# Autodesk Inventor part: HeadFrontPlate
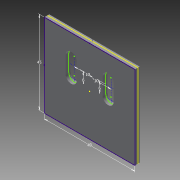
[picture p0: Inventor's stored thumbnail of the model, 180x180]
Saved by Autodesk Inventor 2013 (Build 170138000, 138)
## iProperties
Created: 2013-04
Part Number: HeadFrontPlate
Material: Generic
Document SubType Name: Modeling
Designer: frankenteddy
Density: 1 g/cm^3
Author: frankenteddy
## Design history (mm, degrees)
node "Blocks"
  sketch "Block3"
    geometry: L1 (42.096, -1.116)-(42.096, 7.884); L2 (48.096, 7.884)-(48.096, -1.116); L3 (62.096, -1.116)-(62.096, 7.884); L4 (68.096, 7.884)-(68.096, -1.116); L5 (78.596, -14.116)-(31.596, -14.116); L6 (78.596, 32.884)-(78.596, -14.116); L7 (31.596, 32.884)-(78.596, 32.884); L8 (31.596, -14.116)-(31.596, 32.884); L9 (55.096, -14.116)-(55.096, 32.884); L10 (78.596, 9.384)-(31.596, 9.384); A1 r 3 centre (45.096, 7.884) between (48.096, 7.884) and (42.096, 7.884); A2 r 3 centre (45.096, -1.116) between (42.096, -1.116) and (48.096, -1.116); A3 r 3 centre (65.096, -1.116) between (62.096, -1.116) and (68.096, -1.116); A4 r 3 centre (65.096, 7.884) between (68.096, 7.884) and (62.096, 7.884); 2 further points
    constraints: 20 end point, 8 point on circle, 4 centre point, 4 midpoint
sketch "Sketch1"
  geometry: L1 (-24.5, 22.5)-(24.5, 22.5); L2 (24.5, 22.5)-(24.5, -22.5); L3 (24.5, -22.5)-(-24.5, -22.5); L4 (-24.5, -22.5)-(-24.5, 22.5); 3 further points
  constraints: 8 end point, 2 midpoint, 2 parallel, 1 horizontal, 1 horizontal alignment, 1 perpendicular, 1 vertical alignment
  dimensions: "d0" = 49 distance of L2.end L3.end; "d1" = 45 distance of L1.end L2.end
extrude "Extrusion1" new body sketch "Sketch1" distance "d2" = 1.62; taper "d3" = 0 deg
sketch "Sketch2"
  geometry: L1 (-24.5, -22.5)-(24.5, -22.5) reference; L2 (24.5, -22.5)-(24.5, 22.5) reference; L3 (24.5, 22.5)-(-24.5, 22.5) reference; L4 (-24.5, 22.5)-(-24.5, -22.5) reference; L5 (0, 22.5)-(0, -22.5); L6 (24.5, 0)-(-24.5, 0); L7 (-13, -10.5)-(-13, -1.5); L8 (-7, -1.5)-(-7, -10.5); L9 (7, -10.5)-(7, -1.5); L10 (13, -1.5)-(13, -10.5); L11 (0, -23.5)-(0, 23.5); L12 (23.5, 0)-(-23.5, 0); L13 (-16.531, 18.34)-(0, 18.34); L14 (0, 18.34)-(0, 13.374); L15 (0, 13.374)-(-16.531, 13.374); L16 (-16.531, 13.374)-(-16.531, 18.34); L17 (-9.001, 12.258)-(-6.651, 8.188); L18 (-6.651, 8.188)-(-11.351, 8.188); L19 (-11.351, 8.188)-(-9.001, 12.258); L20 (-7.97, 18.942)-(-10.008, 22.473); L21 (-10.008, 22.473)-(-5.931, 22.473); L22 (-5.931, 22.473)-(-7.97, 18.942); L23 (0, 14.315)-(-4.713, 22.479); L24 (-4.713, 22.479)-(4.713, 22.479); L25 (4.713, 22.479)-(0, 14.315); L26 (-3.247, 12.258)-(-0.897, 8.188); L27 (-0.897, 8.188)-(-5.596, 8.188); L28 (-5.596, 8.188)-(-3.247, 12.258); L29 (-22.323, 0.851)-(-19.711, -2.143); L30 (-19.711, -2.143)-(-22.851, -4.882); L31 (-22.851, -4.882)-(-20.051, -8.092); L32 (-20.051, -8.092)-(-23.425, -11.035); L33 (-19.388, -10.962)-(-16.015, -8.019); L34 (-16.015, -8.019)-(-18.545, -5.119); L35 (-18.545, -5.119)-(-15.51, -2.471); L36 (-15.51, -2.471)-(-18.545, 1.007); L37 (-10, 1.5)-(-10, -13.5); L38 (10, 1.5)-(10, -13.5); L39 (7, -6)-(13, -6); L40 (-7, -6)-(-13, -6); L41 (-18.545, 1.007)-(-17.226, 4.687); L42 (-19.388, -10.962)-(-16.015, -16.078); L43 (-22.323, 0.851)-(-17.226, 4.687); L44 (-16.015, -16.078)-(-23.425, -11.035); L45 (0, 22.5)-(0, -22.5); C1 r 3.587 at (-18.339, 15.894); C2 r 5.941 at (-18.339, 15.894); C3 r 1.247 at (-11.868, 20.707); C4 r 1.839 at (-16.531, 7.036); C5 r 1.413 at (-21.398, 7.812); C6 r 2.671 at (-20.541, -18.762); C7 r 1.818 at (-20.541, -18.762); A1 r 3 centre (-10, -1.5) between (-7, -1.5) and (-13, -1.5); A2 r 3 centre (-10, -10.5) between (-13, -10.5) and (-7, -10.5); A3 r 3 centre (10, -10.5) between (7, -10.5) and (13, -10.5); A4 r 3 centre (10, -1.5) between (13, -1.5) and (7, -1.5); 6 further points
  constraints: 82 end point, 12 point on circle, 11 centre point, 8 midpoint, 6 parallel, 2 collinear, 2 perpendicular, 1 horizontal, 1 point on line, 28 other
  dimensions: "d4" = 10 distance between parallel lines of L5 L37; "d6" = 10 distance between parallel lines of L5 L38; "d9" = 6 distance between parallel lines of L12 L40; "d10" = 6 distance between parallel lines of L12 L39
extrude "Extrusion2" cut sketch "Sketch2" distance "d11" = 1.62; taper "d12" = 0 deg
extrude "Extrusion5" join sketch "Sketch2" distance "d17" = 2; taper "d18" = 0 deg
extrude "Extrusion6" join sketch "Sketch2" distance "d19" = 1; taper "d20" = 0 deg
mirror "Mirror1"
body "Solid1"
sketch "Block2"
  geometry: L1 (-16.531, 18.34)-(0, 18.34); L2 (0, 18.34)-(0, 13.374); L3 (0, 13.374)-(-16.531, 13.374); L4 (-16.531, 13.374)-(-16.531, 18.34); L5 (-9.001, 12.258)-(-6.651, 8.188); L6 (-6.651, 8.188)-(-11.351, 8.188); L7 (-11.351, 8.188)-(-9.001, 12.258); L8 (-7.97, 18.942)-(-10.008, 22.473); L9 (-10.008, 22.473)-(-5.931, 22.473); L10 (-5.931, 22.473)-(-7.97, 18.942); L11 (0, 14.315)-(-4.713, 22.479); L12 (-4.713, 22.479)-(4.713, 22.479); L13 (4.713, 22.479)-(0, 14.315); L14 (-3.247, 12.258)-(-0.897, 8.188); L15 (-0.897, 8.188)-(-5.596, 8.188); L16 (-5.596, 8.188)-(-3.247, 12.258); L17 (-18.371, 3.533)-(-21.398, 0.891); L18 (-21.398, 0.891)-(-18.786, -2.103); L19 (-18.786, -2.103)-(-21.926, -4.842); L20 (-21.926, -4.842)-(-19.126, -8.052); L21 (-19.126, -8.052)-(-22.5, -10.995); L22 (-22.5, -10.995)-(-19.126, -14.862); L23 (-19.126, -14.862)-(-20.813, -10.995); L24 (-20.813, -10.995)-(-17.44, -8.052); L25 (-17.44, -8.052)-(-19.97, -5.152); L26 (-19.97, -5.152)-(-16.935, -2.504); L27 (-16.935, -2.504)-(-19.97, 0.975); L28 (-19.97, 0.975)-(-18.371, 3.533); C1 r 3.587 at (-18.339, 15.894); C2 r 5.941 at (-18.339, 15.894); C3 r 1.247 at (-11.868, 20.707); C4 r 1.839 at (-16.531, 7.036); C5 r 1.413 at (-21.398, 7.812); C6 r 2.671 at (-19.97, -19.404); C7 r 1.818 at (-19.97, -19.404); 5 further points
  constraints: 56 end point, 10 parallel, 7 centre point, 2 coincident, 2 perpendicular, 1 horizontal, 1 point on line, 28 other
node "Block2:2"
